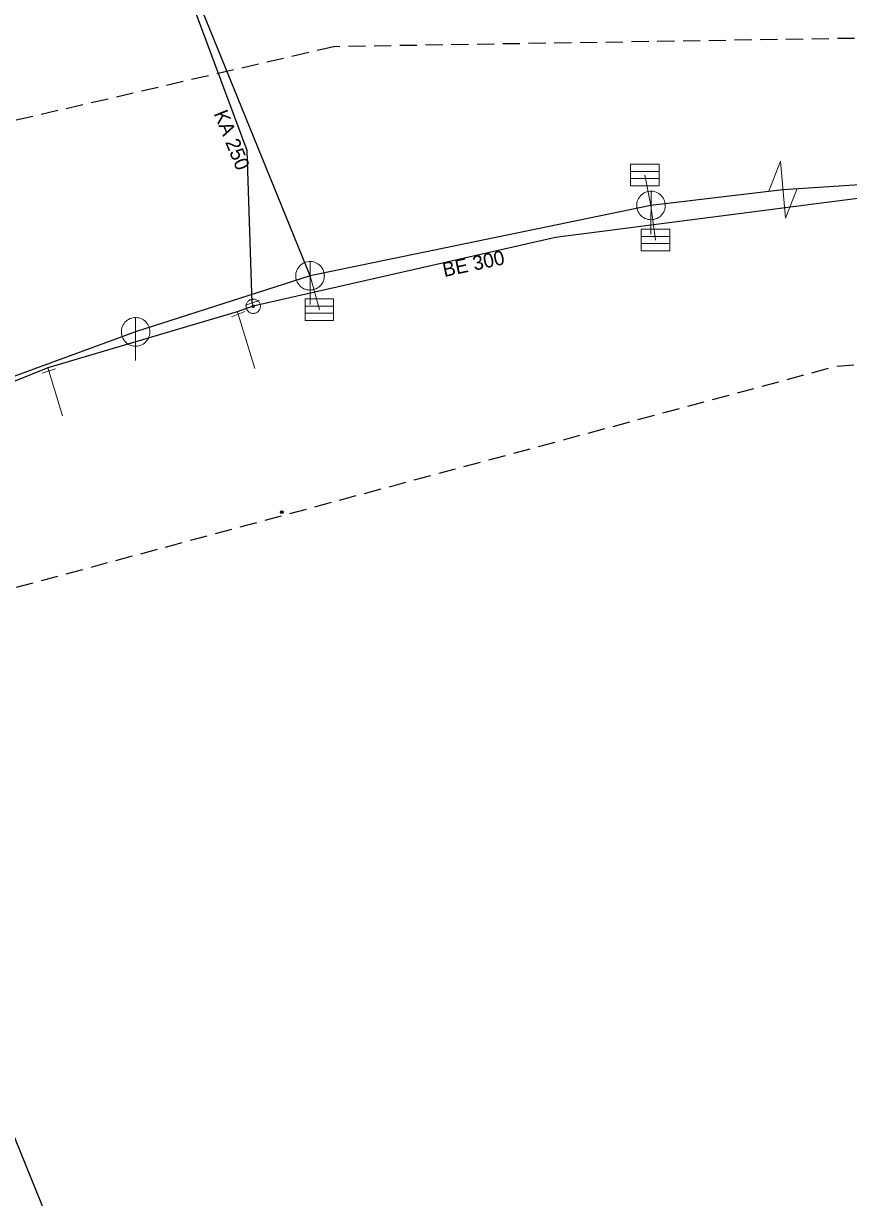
# Model space of a CAD drawing. Extents: x -687387 to -687009, y -972789 to -972578.
# Drawn here: x -687255.8 to -687198.1, y -972748.3 to -972666.2 of the extents above; entities that cross this region are included whole.
import ezdxf

# ---------------------------------------------------------------- set-up
doc = ezdxf.new("R2010")
doc.units = 0
doc.header["$LTSCALE"] = 0.4
doc.header["$PDMODE"] = 32
doc.header["$PDSIZE"] = 0.2
doc.linetypes.add('MEDIUM_DASHED', pattern=[4.5, 3, -1.5])
doc.layers.add('1', color=7, linetype='Continuous')
doc.layers.add('10', color=7, linetype='Continuous')
for name, color, linetype, lineweight in [('11', 7, 'Continuous', 13), ('13', 7, 'Continuous', 13), ('14', 7, 'Continuous', 25), ('17', 7, 'Continuous', 25), ('22', 7, 'Continuous', 13), ('31', 7, 'Continuous', 13), ('34', 7, 'Continuous', 13), ('47', 7, 'Continuous', 13), ('63', 7, 'MEDIUM_DASHED', 25)]:
    doc.layers.add(name, color=color, linetype=linetype, lineweight=lineweight)

msp = doc.modelspace()

# ---------------------------------------------------------------- linework, layer by layer
at = {"layer": '10'}
msp.add_point((-687237.739, -972700.34), dxfattribs=at)
at = {"layer": '11'}
for p, q in [((-687212.354, -972676.769), (-687211.934, -972678.892)), ((-687211.613, -972681.32), (-687211.934, -972678.892)), ((-687235.108, -972686.188), (-687235.77, -972683.813))]:
    msp.add_line(p, q, dxfattribs=at)
at = {"layer": '13'}
for p, q in [((-687240.79, -972686.499), (-687239.62, -972690.296)), ((-687254.032, -972690.468), (-687253.07, -972693.614))]:
    msp.add_line(p, q, dxfattribs=at)
at = {"layer": '14'}
for p, q in [((-687235.77, -972683.813), (-687243.328, -972665.182)), ((-687177.589, -972676.2), (-687202.707, -972677.802)), ((-687202.707, -972677.802), (-687211.934, -972678.892)), ((-687211.934, -972678.892), (-687235.77, -972683.813)), ((-687235.77, -972683.813), (-687247.963, -972687.731)), ((-687247.963, -972687.731), (-687279.968, -972699.493))]:
    msp.add_line(p, q, dxfattribs=at)
at = {"layer": '14', "lineweight": 13}
for p, q in [((-687239.739, -972685.945), (-687239.81, -972685.699)), ((-687240.857, -972686.329), (-687240.79, -972686.499)), ((-687254.098, -972690.259), (-687254.032, -972690.468))]:
    msp.add_line(p, q, dxfattribs=at)
at = {"layer": '17'}
for points in [[(-687239.81, -972685.699), (-687240.168, -972675.043), (-687253.733, -972638.624), (-687267.199, -972604.19)], [(-687140.419, -972674.734), (-687161.655, -972677.153), (-687161.956, -972677.145), (-687194.054, -972677.975), (-687218.609, -972681.129), (-687239.739, -972685.945)], [(-687239.739, -972685.945), (-687240.857, -972686.329), (-687254.098, -972690.259), (-687282.85, -972701.854), (-687288.604, -972703.811)], [(-687233.122, -972789.445), (-687233.831, -972788.864), (-687238.279, -972783.932), (-687244.316, -972773.96), (-687260.423, -972734.254), (-687276.818, -972714.934), (-687281.462, -972710.697), (-687283.483, -972709.333)]]:
    msp.add_lwpolyline(points, dxfattribs=at)
at = {"layer": '22'}
for p, q in [((-687213.365, -972676.512), (-687211.365, -972676.512)), ((-687213.365, -972677.012), (-687211.365, -972677.012)), ((-687211.934, -972680.892), (-687211.933, -972677.892)), ((-687212.624, -972681.063), (-687210.624, -972681.063)), ((-687212.624, -972681.563), (-687210.624, -972681.563)), ((-687235.77, -972685.813), (-687235.769, -972682.813)), ((-687236.119, -972685.931), (-687234.119, -972685.931)), ((-687236.119, -972686.431), (-687234.119, -972686.431)), ((-687247.963, -972689.731), (-687247.962, -972686.731))]:
    msp.add_line(p, q, dxfattribs=at)
for points in [[(-687213.365, -972676.012), (-687211.365, -972676.012), (-687211.365, -972677.512), (-687213.365, -972677.512)], [(-687210.934, -972678.892), (-687210.939, -972678.783), (-687210.957, -972678.675), (-687210.987, -972678.569), (-687211.027, -972678.468), (-687211.079, -972678.371), (-687211.141, -972678.281), (-687211.213, -972678.198), (-687211.293, -972678.124), (-687211.381, -972678.058), (-687211.475, -972678.003), (-687211.575, -972677.958), (-687211.68, -972677.925), (-687211.787, -972677.903), (-687211.896, -972677.893), (-687212.006, -972677.895), (-687212.114, -972677.909), (-687212.221, -972677.934), (-687212.324, -972677.971), (-687212.422, -972678.02), (-687212.514, -972678.078), (-687212.6, -972678.147), (-687212.677, -972678.224), (-687212.746, -972678.31), (-687212.805, -972678.402), (-687212.853, -972678.5), (-687212.89, -972678.603), (-687212.916, -972678.71), (-687212.93, -972678.818), (-687212.933, -972678.928), (-687212.923, -972679.037), (-687212.902, -972679.144), (-687212.868, -972679.248), (-687212.824, -972679.348), (-687212.769, -972679.443), (-687212.703, -972679.531), (-687212.629, -972679.611), (-687212.546, -972679.683), (-687212.456, -972679.745), (-687212.36, -972679.797), (-687212.258, -972679.838), (-687212.153, -972679.868), (-687212.045, -972679.886), (-687211.935, -972679.892), (-687211.826, -972679.886), (-687211.718, -972679.868), (-687211.613, -972679.839), (-687211.511, -972679.798), (-687211.414, -972679.746), (-687211.324, -972679.684), (-687211.241, -972679.613), (-687211.166, -972679.533), (-687211.101, -972679.445), (-687211.045, -972679.351), (-687211.001, -972679.251), (-687210.967, -972679.147), (-687210.945, -972679.039), (-687210.935, -972678.93)], [(-687212.624, -972680.563), (-687210.624, -972680.563), (-687210.624, -972682.063), (-687212.624, -972682.063)], [(-687234.77, -972683.813), (-687234.775, -972683.704), (-687234.793, -972683.596), (-687234.823, -972683.49), (-687234.863, -972683.389), (-687234.915, -972683.292), (-687234.977, -972683.202), (-687235.049, -972683.119), (-687235.129, -972683.045), (-687235.217, -972682.979), (-687235.311, -972682.924), (-687235.411, -972682.879), (-687235.516, -972682.846), (-687235.623, -972682.824), (-687235.732, -972682.814), (-687235.842, -972682.816), (-687235.95, -972682.83), (-687236.057, -972682.855), (-687236.16, -972682.892), (-687236.258, -972682.941), (-687236.35, -972682.999), (-687236.436, -972683.068), (-687236.513, -972683.145), (-687236.582, -972683.231), (-687236.641, -972683.323), (-687236.689, -972683.421), (-687236.726, -972683.524), (-687236.752, -972683.631), (-687236.766, -972683.739), (-687236.769, -972683.849), (-687236.759, -972683.958), (-687236.738, -972684.065), (-687236.704, -972684.169), (-687236.66, -972684.269), (-687236.605, -972684.364), (-687236.539, -972684.452), (-687236.465, -972684.532), (-687236.382, -972684.604), (-687236.292, -972684.666), (-687236.196, -972684.718), (-687236.094, -972684.759), (-687235.989, -972684.789), (-687235.881, -972684.807), (-687235.771, -972684.813), (-687235.662, -972684.807), (-687235.554, -972684.789), (-687235.449, -972684.76), (-687235.347, -972684.719), (-687235.25, -972684.667), (-687235.16, -972684.605), (-687235.077, -972684.534), (-687235.002, -972684.454), (-687234.937, -972684.366), (-687234.881, -972684.272), (-687234.837, -972684.172), (-687234.803, -972684.068), (-687234.781, -972683.96), (-687234.771, -972683.851)], [(-687236.119, -972685.431), (-687234.119, -972685.431), (-687234.119, -972686.931), (-687236.119, -972686.931)], [(-687246.963, -972687.731), (-687246.968, -972687.622), (-687246.986, -972687.514), (-687247.016, -972687.408), (-687247.056, -972687.307), (-687247.108, -972687.21), (-687247.17, -972687.12), (-687247.242, -972687.037), (-687247.322, -972686.963), (-687247.41, -972686.897), (-687247.504, -972686.842), (-687247.604, -972686.797), (-687247.709, -972686.764), (-687247.816, -972686.742), (-687247.925, -972686.732), (-687248.035, -972686.734), (-687248.143, -972686.748), (-687248.25, -972686.773), (-687248.353, -972686.81), (-687248.451, -972686.859), (-687248.543, -972686.917), (-687248.629, -972686.986), (-687248.706, -972687.063), (-687248.775, -972687.149), (-687248.834, -972687.241), (-687248.882, -972687.339), (-687248.919, -972687.442), (-687248.945, -972687.549), (-687248.959, -972687.657), (-687248.962, -972687.767), (-687248.952, -972687.876), (-687248.931, -972687.983), (-687248.897, -972688.087), (-687248.853, -972688.187), (-687248.798, -972688.282), (-687248.732, -972688.37), (-687248.658, -972688.45), (-687248.575, -972688.522), (-687248.485, -972688.584), (-687248.389, -972688.636), (-687248.287, -972688.677), (-687248.182, -972688.707), (-687248.074, -972688.725), (-687247.964, -972688.731), (-687247.855, -972688.725), (-687247.747, -972688.707), (-687247.642, -972688.678), (-687247.54, -972688.637), (-687247.443, -972688.585), (-687247.353, -972688.523), (-687247.27, -972688.452), (-687247.195, -972688.372), (-687247.13, -972688.284), (-687247.074, -972688.19), (-687247.03, -972688.09), (-687246.996, -972687.986), (-687246.974, -972687.878), (-687246.964, -972687.769)]]:
    msp.add_lwpolyline(points, close=True, dxfattribs=at)
at = {"layer": '31'}
msp.add_lwpolyline([(-687203.703, -972677.887), (-687202.877, -972675.809), (-687202.536, -972679.795), (-687201.71, -972677.717)], dxfattribs=at)
at = {"layer": '34'}
for p, q in [((-687239.336, -972685.536), (-687240.281, -972685.862)), ((-687240.325, -972686.313), (-687241.254, -972686.683)), ((-687253.555, -972690.315), (-687254.508, -972690.619))]:
    msp.add_line(p, q, dxfattribs=at)
at = {"layer": '47'}
for points in [[(-687239.24, -972685.902), (-687239.248, -972685.851), (-687239.26, -972685.8), (-687239.278, -972685.751), (-687239.3, -972685.704), (-687239.328, -972685.659), (-687239.361, -972685.617), (-687239.397, -972685.58), (-687239.437, -972685.547), (-687239.48, -972685.517), (-687239.526, -972685.492), (-687239.575, -972685.472), (-687239.625, -972685.458), (-687239.676, -972685.448), (-687239.729, -972685.445), (-687239.781, -972685.446), (-687239.832, -972685.454), (-687239.883, -972685.466), (-687239.933, -972685.484), (-687239.979, -972685.506), (-687240.024, -972685.534), (-687240.066, -972685.567), (-687240.104, -972685.603), (-687240.137, -972685.643), (-687240.167, -972685.686), (-687240.191, -972685.732), (-687240.211, -972685.781), (-687240.226, -972685.831), (-687240.235, -972685.882), (-687240.238, -972685.935), (-687240.237, -972685.987), (-687240.229, -972686.038), (-687240.217, -972686.089), (-687240.2, -972686.139), (-687240.177, -972686.185), (-687240.149, -972686.23), (-687240.117, -972686.272), (-687240.081, -972686.31), (-687240.041, -972686.343), (-687239.997, -972686.373), (-687239.951, -972686.397), (-687239.902, -972686.417), (-687239.853, -972686.432), (-687239.801, -972686.441), (-687239.748, -972686.444), (-687239.696, -972686.443), (-687239.645, -972686.435), (-687239.594, -972686.423), (-687239.545, -972686.406), (-687239.498, -972686.383), (-687239.453, -972686.355), (-687239.411, -972686.323), (-687239.374, -972686.287), (-687239.341, -972686.247), (-687239.311, -972686.203), (-687239.286, -972686.157), (-687239.266, -972686.108), (-687239.252, -972686.059), (-687239.242, -972686.007), (-687239.239, -972685.954)], [(-687239.657, -972685.938), (-687239.658, -972685.929), (-687239.66, -972685.921), (-687239.663, -972685.913), (-687239.667, -972685.905), (-687239.671, -972685.898), (-687239.677, -972685.891), (-687239.682, -972685.885), (-687239.689, -972685.879), (-687239.696, -972685.875), (-687239.704, -972685.87), (-687239.712, -972685.867), (-687239.72, -972685.865), (-687239.728, -972685.863), (-687239.736, -972685.862), (-687239.745, -972685.863), (-687239.754, -972685.864), (-687239.762, -972685.866), (-687239.77, -972685.869), (-687239.778, -972685.873), (-687239.785, -972685.877), (-687239.792, -972685.883), (-687239.798, -972685.888), (-687239.804, -972685.895), (-687239.809, -972685.902), (-687239.813, -972685.91), (-687239.816, -972685.918), (-687239.818, -972685.926), (-687239.82, -972685.934), (-687239.821, -972685.942), (-687239.82, -972685.951), (-687239.819, -972685.96), (-687239.817, -972685.968), (-687239.814, -972685.976), (-687239.81, -972685.984), (-687239.806, -972685.991), (-687239.801, -972685.998), (-687239.795, -972686.004), (-687239.788, -972686.01), (-687239.781, -972686.015), (-687239.773, -972686.019), (-687239.765, -972686.022), (-687239.757, -972686.024), (-687239.749, -972686.026), (-687239.741, -972686.027), (-687239.732, -972686.026), (-687239.723, -972686.025), (-687239.715, -972686.023), (-687239.707, -972686.02), (-687239.699, -972686.016), (-687239.692, -972686.012), (-687239.685, -972686.007), (-687239.679, -972686.001), (-687239.673, -972685.994), (-687239.669, -972685.987), (-687239.664, -972685.979), (-687239.661, -972685.971), (-687239.659, -972685.963), (-687239.657, -972685.955), (-687239.656, -972685.947)]]:
    msp.add_lwpolyline(points, close=True, dxfattribs=at)
at = {"layer": '63'}
msp.add_lwpolyline([(-687147.303, -972666.399), (-687234.11, -972667.795), (-687234.11, -972667.795), (-687256.998, -972673.098), (-687256.998, -972673.098), (-687289.655, -972689.845), (-687289.655, -972689.845), (-687341.85, -972711.338), (-687341.85, -972711.338), (-687347.712, -972701.568), (-687347.712, -972701.568), (-687372.554, -972712.454), (-687357.202, -972748.182), (-687357.202, -972748.182), (-687324.545, -972735.9), (-687324.545, -972735.9), (-687325.103, -972730.318), (-687325.103, -972730.318), (-687291.05, -972714.966), (-687291.05, -972714.966), (-687198.94, -972690.124), (-687198.94, -972690.124), (-687142.558, -972685.938)], dxfattribs=at)

# ---------------------------------------------------------------- texts
at = {"layer": '1'}
for s, rotation, p in [('KA 250', 292, (-687242.516, -972672.464)), ('BE 300', 12, (-687226.388, -972683.903))]:
    msp.add_text(s, height=1, rotation=rotation, dxfattribs=at).set_placement(p)

doc.saveas('drawing.dxf')
